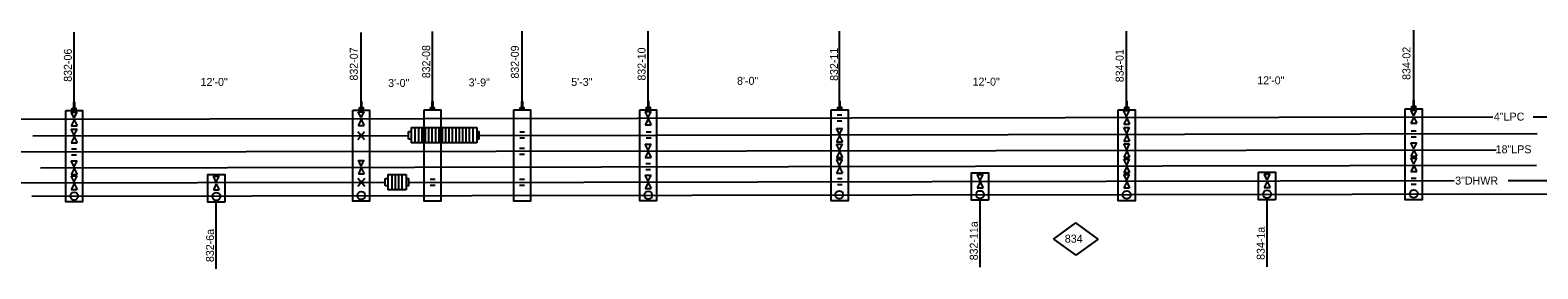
# Model space of a CAD drawing. Extents: x 9888 to 10178, y 10284 to 10314.
# Drawn here: x 9975.1 to 10038.1, y 10285.8 to 10295.8 of the extents above; entities that cross this region are included whole.
import ezdxf

# ---------------------------------------------------------------- set-up
doc = ezdxf.new("R2010")
doc.units = 0
for name, color, linetype in [('Level 51', 7, 'Continuous'), ('M-EQPM-N', 7, 'Continuous'), ('M-STEM-CONP', 7, 'Continuous'), ('M-STEM-CONP-N', 7, 'Continuous'), ('P-CMPA-PIPE', 7, 'Continuous'), ('P-CMPA-PIPE-N', 7, 'Continuous'), ('P-DOMW-HPIP-N', 7, 'Continuous')]:
    doc.layers.add(name, color=color, linetype=linetype)

msp = doc.modelspace()

# ---------------------------------------------------------------- linework, layer by layer
at = {"layer": 'Level 51'}
for p, q in [((9973.612, 10292.107), (10036.2, 10292.214)), ((9976.894, 10292.162), (9976.77, 10292.41)), ((9976.77, 10292.41), (9977.018, 10292.41)), ((9976.896, 10292.085), (9976.772, 10291.838)), ((9976.894, 10292.162), (9977.018, 10292.41)), ((9976.896, 10292.085), (9977.02, 10291.838)), ((9988.894, 10292.178), (9988.77, 10292.425)), ((9988.77, 10292.425), (9989.018, 10292.425)), ((9988.896, 10292.101), (9988.772, 10291.853)), ((9988.894, 10292.178), (9989.018, 10292.425)), ((9988.896, 10292.101), (9989.02, 10291.853)), ((10000.896, 10292.186), (10000.772, 10292.434)), ((10000.772, 10292.434), (10001.02, 10292.434)), ((10000.896, 10292.117), (10000.772, 10291.869)), ((10000.896, 10292.186), (10001.02, 10292.434)), ((10000.896, 10292.117), (10001.02, 10291.869)), ((10008.788, 10292.295), (10008.992, 10292.295)), ((10020.894, 10292.224), (10020.77, 10292.472)), ((10020.77, 10292.472), (10021.017, 10292.472)), ((10020.896, 10292.151), (10020.772, 10291.903)), ((10020.894, 10292.224), (10021.017, 10292.472)), ((10020.896, 10292.151), (10021.02, 10291.903)), ((10032.895, 10292.247), (10032.771, 10292.495)), ((10032.771, 10292.495), (10033.019, 10292.495)), ((10032.896, 10292.192), (10032.772, 10291.945)), ((10032.895, 10292.247), (10033.019, 10292.495)), ((10032.896, 10292.192), (10033.02, 10291.945)), ((10037.895, 10292.216), (10071.644, 10292.241)), ((9976.772, 10291.838), (9977.02, 10291.838)), ((9988.772, 10291.853), (9989.02, 10291.853)), ((10000.772, 10291.869), (10001.02, 10291.869)), ((10008.788, 10292.045), (10008.992, 10292.045)), ((10020.772, 10291.903), (10021.02, 10291.903)), ((10032.772, 10291.945), (10033.02, 10291.945)), ((10017.843, 10287.09), (10018.776, 10287.762)), ((10019.709, 10287.09), (10018.776, 10287.762)), ((10017.843, 10287.09), (10018.776, 10286.418)), ((10019.709, 10287.09), (10018.776, 10286.418))]:
    msp.add_line(p, q, dxfattribs=at)
at = {"layer": 'M-EQPM-N'}
for p, q in [((10032.895, 10292.552), (10032.895, 10295.846)), ((9976.895, 10292.479), (9976.895, 10295.758)), ((9988.895, 10292.494), (9988.895, 10295.742)), ((9991.874, 10292.499), (9991.874, 10295.793)), ((9995.624, 10292.503), (9995.624, 10295.798)), ((10000.895, 10292.51), (10000.895, 10295.805)), ((10008.895, 10292.51), (10008.895, 10295.805)), ((10020.895, 10292.51), (10020.895, 10295.805)), ((9982.837, 10285.837), (9982.837, 10288.639)), ((10014.767, 10285.909), (10014.767, 10288.712)), ((10026.764, 10285.928), (10026.764, 10288.73))]:
    msp.add_line(p, q, dxfattribs=at)
for points in [[(9976.542, 10292.479), (9977.247, 10292.479), (9977.247, 10288.655), (9976.542, 10288.655)], [(9988.542, 10292.494), (9989.247, 10292.494), (9989.247, 10288.671), (9988.542, 10288.671)], [(9991.521, 10292.499), (9992.226, 10292.499), (9992.226, 10288.675), (9991.521, 10288.675)], [(9995.271, 10292.503), (9995.976, 10292.503), (9995.976, 10288.679), (9995.271, 10288.679)], [(10000.542, 10292.51), (10001.247, 10292.51), (10001.247, 10288.686), (10000.542, 10288.686)], [(10008.542, 10292.51), (10009.247, 10292.51), (10009.247, 10288.686), (10008.542, 10288.686)], [(10020.542, 10292.51), (10021.247, 10292.51), (10021.247, 10288.686), (10020.542, 10288.686)], [(10032.542, 10292.552), (10033.247, 10292.552), (10033.247, 10288.728), (10032.542, 10288.728)], [(9983.19, 10288.639), (9982.485, 10288.639), (9982.485, 10289.794), (9983.19, 10289.794)], [(10015.12, 10288.712), (10014.415, 10288.712), (10014.415, 10289.867), (10015.12, 10289.867)], [(10027.116, 10288.73), (10026.411, 10288.73), (10026.411, 10289.885), (10027.116, 10289.885)]]:
    msp.add_lwpolyline(points, close=True, dxfattribs=at)
at = {"layer": 'M-STEM-CONP'}
for p, q in [((9975.171, 10291.408), (9990.87, 10291.433)), ((9976.896, 10291.444), (9976.772, 10291.691)), ((9976.772, 10291.691), (9977.02, 10291.691)), ((9976.896, 10291.444), (9977.02, 10291.691)), ((9988.749, 10291.26), (9989.04, 10291.6)), ((9988.749, 10291.6), (9989.04, 10291.26)), ((9990.87, 10291.281), (9990.87, 10291.595)), ((9990.87, 10291.595), (9990.978, 10291.595)), ((9990.981, 10291.761), (9993.725, 10291.759)), ((9990.981, 10291.761), (9990.981, 10291.115)), ((9991.144, 10291.755), (9991.144, 10291.11)), ((9991.286, 10291.755), (9991.286, 10291.11)), ((9991.428, 10291.755), (9991.428, 10291.11)), ((9991.57, 10291.755), (9991.57, 10291.11)), ((9991.712, 10291.755), (9991.712, 10291.11)), ((9991.854, 10291.755), (9991.854, 10291.11)), ((9991.996, 10291.755), (9991.996, 10291.11)), ((9992.138, 10291.755), (9992.138, 10291.11)), ((9992.28, 10291.755), (9992.28, 10291.11)), ((9992.421, 10291.755), (9992.421, 10291.11)), ((9992.563, 10291.755), (9992.563, 10291.11)), ((9992.705, 10291.755), (9992.705, 10291.11)), ((9992.847, 10291.755), (9992.847, 10291.11)), ((9992.989, 10291.755), (9992.989, 10291.11)), ((9993.131, 10291.755), (9993.131, 10291.11)), ((9993.273, 10291.755), (9993.273, 10291.11)), ((9993.415, 10291.755), (9993.415, 10291.11)), ((9993.557, 10291.755), (9993.557, 10291.11)), ((9993.725, 10291.759), (9993.725, 10291.114)), ((9993.725, 10291.594), (9993.832, 10291.594)), ((9993.832, 10291.279), (9993.832, 10291.594)), ((9993.832, 10291.434), (10038.058, 10291.509)), ((9995.522, 10291.577), (9995.726, 10291.577)), ((10000.81, 10291.575), (10001.014, 10291.575)), ((10008.896, 10291.481), (10008.772, 10291.728)), ((10008.772, 10291.728), (10009.02, 10291.728)), ((10008.896, 10291.481), (10009.02, 10291.728)), ((10020.896, 10291.509), (10020.772, 10291.757)), ((10020.772, 10291.757), (10021.02, 10291.757)), ((10020.896, 10291.44), (10020.772, 10291.192)), ((10020.896, 10291.509), (10021.02, 10291.757)), ((10020.896, 10291.44), (10021.02, 10291.192)), ((10032.791, 10291.626), (10032.995, 10291.626)), ((9976.896, 10291.374), (9976.772, 10291.126)), ((9976.772, 10291.126), (9977.02, 10291.126)), ((9976.896, 10291.374), (9977.02, 10291.126)), ((9990.978, 10291.281), (9990.87, 10291.281)), ((9993.725, 10291.114), (9990.981, 10291.115)), ((9993.832, 10291.279), (9993.725, 10291.279)), ((9995.522, 10291.327), (9995.726, 10291.327)), ((10000.81, 10291.325), (10001.014, 10291.325)), ((10008.896, 10291.411), (10008.772, 10291.163)), ((10008.772, 10291.163), (10009.02, 10291.163)), ((10008.896, 10291.411), (10009.02, 10291.163)), ((10020.772, 10291.192), (10021.02, 10291.192)), ((10032.791, 10291.376), (10032.995, 10291.376))]:
    msp.add_line(p, q, dxfattribs=at)
at = {"layer": 'M-STEM-CONP-N'}
for p, q in [((9971.06, 10290.733), (10036.349, 10290.833)), ((9976.79, 10290.863), (9976.994, 10290.863)), ((9995.514, 10290.894), (9995.718, 10290.894)), ((10000.896, 10290.817), (10000.772, 10291.065)), ((10000.772, 10291.065), (10001.02, 10291.065)), ((10000.896, 10290.817), (10001.02, 10291.065)), ((10008.896, 10290.817), (10008.772, 10291.065)), ((10008.772, 10291.065), (10009.02, 10291.065)), ((10008.896, 10290.817), (10009.02, 10291.065)), ((10020.896, 10290.834), (10020.772, 10291.082)), ((10020.772, 10291.082), (10021.02, 10291.082)), ((10020.896, 10290.834), (10021.02, 10291.082)), ((10032.896, 10290.876), (10032.772, 10291.124)), ((10032.772, 10291.124), (10033.02, 10291.124)), ((10032.896, 10290.807), (10032.772, 10290.559)), ((10032.896, 10290.876), (10033.02, 10291.124)), ((10032.896, 10290.807), (10033.02, 10290.559)), ((9976.79, 10290.613), (9976.994, 10290.613)), ((9995.514, 10290.644), (9995.718, 10290.644)), ((10000.896, 10290.748), (10000.772, 10290.5)), ((10000.772, 10290.5), (10001.02, 10290.5)), ((10000.896, 10290.748), (10001.02, 10290.5)), ((10008.896, 10290.748), (10008.772, 10290.5)), ((10008.772, 10290.5), (10009.02, 10290.5)), ((10008.896, 10290.748), (10009.02, 10290.5)), ((10020.896, 10290.765), (10020.772, 10290.517)), ((10020.772, 10290.517), (10021.02, 10290.517)), ((10020.896, 10290.765), (10021.02, 10290.517)), ((10032.772, 10290.559), (10033.02, 10290.559))]:
    msp.add_line(p, q, dxfattribs=at)
at = {"layer": 'P-CMPA-PIPE'}
for points in [[(9976.874, 10292.583), (9976.921, 10292.583), (9976.921, 10292.818), (9976.874, 10292.818)], [(9988.874, 10292.598), (9988.921, 10292.598), (9988.921, 10292.834), (9988.874, 10292.834)], [(9991.853, 10292.603), (9991.9, 10292.603), (9991.9, 10292.838), (9991.853, 10292.838)], [(9995.603, 10292.607), (9995.65, 10292.607), (9995.65, 10292.843), (9995.603, 10292.843)], [(10000.874, 10292.614), (10000.921, 10292.614), (10000.921, 10292.849), (10000.874, 10292.849)], [(10008.874, 10292.614), (10008.921, 10292.614), (10008.921, 10292.849), (10008.874, 10292.849)], [(10020.874, 10292.614), (10020.921, 10292.614), (10020.921, 10292.849), (10020.874, 10292.849)], [(10032.874, 10292.656), (10032.921, 10292.656), (10032.921, 10292.891), (10032.874, 10292.891)], [(9976.818, 10292.579), (9976.971, 10292.579), (9976.971, 10292.479), (9976.818, 10292.479)], [(9988.818, 10292.595), (9988.971, 10292.595), (9988.971, 10292.494), (9988.818, 10292.494)], [(9991.798, 10292.599), (9991.95, 10292.599), (9991.95, 10292.499), (9991.798, 10292.499)], [(9995.548, 10292.603), (9995.7, 10292.603), (9995.7, 10292.503), (9995.548, 10292.503)], [(10000.818, 10292.61), (10000.971, 10292.61), (10000.971, 10292.51), (10000.818, 10292.51)], [(10008.818, 10292.61), (10008.971, 10292.61), (10008.971, 10292.51), (10008.818, 10292.51)], [(10020.818, 10292.61), (10020.971, 10292.61), (10020.971, 10292.51), (10020.818, 10292.51)], [(10032.818, 10292.652), (10032.971, 10292.652), (10032.971, 10292.552), (10032.818, 10292.552)]]:
    msp.add_lwpolyline(points, close=True, dxfattribs=at)
at = {"layer": 'P-CMPA-PIPE-N'}
msp.add_line((9975.124, 10288.884), (10040.708, 10288.99), dxfattribs=at)
for centre in [(9976.896, 10288.892), (9982.839, 10288.877), (9988.896, 10288.908), (10008.883, 10288.943), (10014.768, 10288.949), (10020.896, 10288.941), (10026.765, 10288.968), (10032.896, 10288.982)]:
    msp.add_circle(centre, 0.167, dxfattribs=at)
at = {"layer": 'P-DOMW-HPIP-N'}
for p, q in [((9975.485, 10290.074), (10038.025, 10290.18)), ((9976.896, 10290.112), (9976.772, 10290.36)), ((9976.772, 10290.36), (9977.02, 10290.36)), ((9976.896, 10290.112), (9977.02, 10290.36)), ((9988.9, 10290.145), (9988.776, 10290.393)), ((9988.776, 10290.383), (9989.024, 10290.383)), ((9988.9, 10290.145), (9989.024, 10290.393)), ((10000.788, 10290.252), (10000.992, 10290.252)), ((10008.896, 10290.174), (10008.772, 10290.421)), ((10008.772, 10290.421), (10009.02, 10290.421)), ((10008.896, 10290.174), (10009.02, 10290.421)), ((10020.896, 10290.191), (10020.772, 10290.439)), ((10020.772, 10290.439), (10021.02, 10290.439)), ((10020.896, 10290.191), (10021.02, 10290.439)), ((10032.896, 10290.232), (10032.772, 10290.48)), ((10032.772, 10290.48), (10033.02, 10290.48)), ((10032.896, 10290.163), (10032.772, 10289.915)), ((10032.896, 10290.232), (10033.02, 10290.48)), ((10032.896, 10290.163), (10033.02, 10289.915)), ((9976.896, 10290.042), (9976.772, 10289.794)), ((9976.772, 10289.794), (9977.02, 10289.794)), ((9976.896, 10289.489), (9976.772, 10289.737)), ((9976.772, 10289.737), (9977.02, 10289.737)), ((9976.896, 10290.042), (9977.02, 10289.794)), ((9976.896, 10289.489), (9977.02, 10289.737)), ((9982.839, 10289.474), (9982.715, 10289.722)), ((9982.715, 10289.722), (9982.963, 10289.722)), ((9982.839, 10289.474), (9982.963, 10289.722)), ((9988.755, 10289.299), (9989.047, 10289.639)), ((9988.755, 10289.639), (9989.047, 10289.299)), ((9988.9, 10290.076), (9988.776, 10289.828)), ((9988.776, 10289.828), (9989.024, 10289.828)), ((9988.9, 10290.076), (9989.024, 10289.828)), ((9989.896, 10289.313), (9989.896, 10289.627)), ((9989.896, 10289.627), (9990.003, 10289.627)), ((9990.006, 10289.793), (9990.782, 10289.793)), ((9990.006, 10289.793), (9990.006, 10289.148)), ((9990.17, 10289.793), (9990.17, 10289.148)), ((9990.311, 10289.793), (9990.311, 10289.148)), ((9990.453, 10289.793), (9990.453, 10289.148)), ((9990.595, 10289.793), (9990.595, 10289.148)), ((9990.782, 10289.793), (9990.782, 10289.148)), ((9990.782, 10289.627), (9990.889, 10289.627)), ((9990.889, 10289.313), (9990.889, 10289.627)), ((9990.889, 10289.466), (9990.889, 10289.627)), ((9990.93, 10289.463), (10034.582, 10289.538)), ((9991.785, 10289.596), (9991.989, 10289.596)), ((9995.52, 10289.596), (9995.724, 10289.596)), ((10000.896, 10289.521), (10000.772, 10289.768)), ((10000.772, 10289.768), (10001.02, 10289.768)), ((10000.788, 10290.002), (10000.992, 10290.002)), ((10000.896, 10289.521), (10001.02, 10289.768)), ((10008.896, 10290.104), (10008.772, 10289.856)), ((10008.772, 10289.856), (10009.02, 10289.856)), ((10008.805, 10289.622), (10009.009, 10289.622)), ((10008.896, 10290.104), (10009.02, 10289.856)), ((10014.769, 10289.546), (10014.645, 10289.794)), ((10014.645, 10289.794), (10014.892, 10289.794)), ((10014.769, 10289.546), (10014.892, 10289.794)), ((10020.896, 10290.121), (10020.772, 10289.873)), ((10020.772, 10289.873), (10021.02, 10289.873)), ((10020.896, 10289.55), (10020.772, 10289.797)), ((10020.772, 10289.797), (10021.02, 10289.797)), ((10020.896, 10290.121), (10021.02, 10289.873)), ((10020.896, 10289.55), (10021.02, 10289.797)), ((10026.765, 10289.565), (10026.641, 10289.813)), ((10026.641, 10289.813), (10026.889, 10289.813)), ((10026.765, 10289.565), (10026.889, 10289.813)), ((10032.772, 10289.915), (10033.02, 10289.915)), ((10032.791, 10289.644), (10032.995, 10289.644)), ((10036.846, 10289.542), (10071.655, 10289.568)), ((9974.223, 10289.45), (9989.896, 10289.47)), ((9976.896, 10289.42), (9976.772, 10289.172)), ((9976.772, 10289.172), (9977.02, 10289.172)), ((9976.896, 10289.42), (9977.02, 10289.172)), ((9982.839, 10289.404), (9982.715, 10289.157)), ((9982.715, 10289.157), (9982.963, 10289.157)), ((9982.839, 10289.404), (9982.963, 10289.157)), ((9990.003, 10289.313), (9989.896, 10289.313)), ((9990.782, 10289.148), (9990.006, 10289.148)), ((9990.889, 10289.313), (9990.782, 10289.313)), ((9991.785, 10289.346), (9991.989, 10289.346)), ((9995.52, 10289.346), (9995.724, 10289.346)), ((10000.896, 10289.451), (10000.772, 10289.203)), ((10000.772, 10289.203), (10001.02, 10289.203)), ((10000.896, 10289.451), (10001.02, 10289.203)), ((10008.805, 10289.372), (10009.009, 10289.372)), ((10014.769, 10289.477), (10014.645, 10289.229)), ((10014.645, 10289.229), (10014.892, 10289.229)), ((10014.769, 10289.477), (10014.892, 10289.229)), ((10020.896, 10289.48), (10020.772, 10289.232)), ((10020.772, 10289.232), (10021.02, 10289.232)), ((10020.896, 10289.48), (10021.02, 10289.232)), ((10026.765, 10289.495), (10026.641, 10289.248)), ((10026.641, 10289.248), (10026.889, 10289.248)), ((10026.765, 10289.495), (10026.889, 10289.248)), ((10032.791, 10289.394), (10032.995, 10289.394))]:
    msp.add_line(p, q, dxfattribs=at)
msp.add_circle((10000.896, 10288.923), 0.167, dxfattribs=at)

# ---------------------------------------------------------------- texts
at = {"layer": 'Level 51'}
for s, p in [('4"LPC', (10036.248, 10292.054)), ('834', (10018.31, 10286.938))]:
    msp.add_text(s, height=0.3333, dxfattribs=at).set_placement(p)
at = {"layer": 'M-EQPM-N'}
for s, p in [('832-06', (9976.799, 10293.679)), ('832-07', (9988.753, 10293.73)), ('832-08', (9991.779, 10293.828)), ('832-09', (9995.485, 10293.813)), ('832-10', (10000.783, 10293.729)), ('832-11', (10008.829, 10293.717)), ('834-01', (10020.77, 10293.659)), ('834-02', (10032.759, 10293.758)), ('832-11a', (10014.671, 10286.197)), ('832-6a', (9982.741, 10286.124)), ('834-1a', (10026.668, 10286.215))]:
    msp.add_text(s, height=0.3333, rotation=90, dxfattribs=at).set_placement(p)
for s, p in [('12\'-0"', (9982.181, 10293.505)), ('3\'-0"', (9990.021, 10293.463)), ('3\'-9"', (9993.387, 10293.485)), ('5\'-3"', (9997.676, 10293.507)), ('8\'-0"', (10004.608, 10293.552)), ('12\'-0"', (10014.455, 10293.517)), ('12\'-0"', (10026.355, 10293.573))]:
    msp.add_text(s, height=0.3333, dxfattribs=at).set_placement(p)
at = {"layer": 'M-STEM-CONP-N'}
msp.add_text('18"LPS', height=0.3333, dxfattribs=at).set_placement((10036.321, 10290.684))
at = {"layer": 'P-DOMW-HPIP-N'}
msp.add_text('3"DHWR', height=0.3333, dxfattribs=at).set_placement((10034.63, 10289.373))

doc.saveas('drawing.dxf')
